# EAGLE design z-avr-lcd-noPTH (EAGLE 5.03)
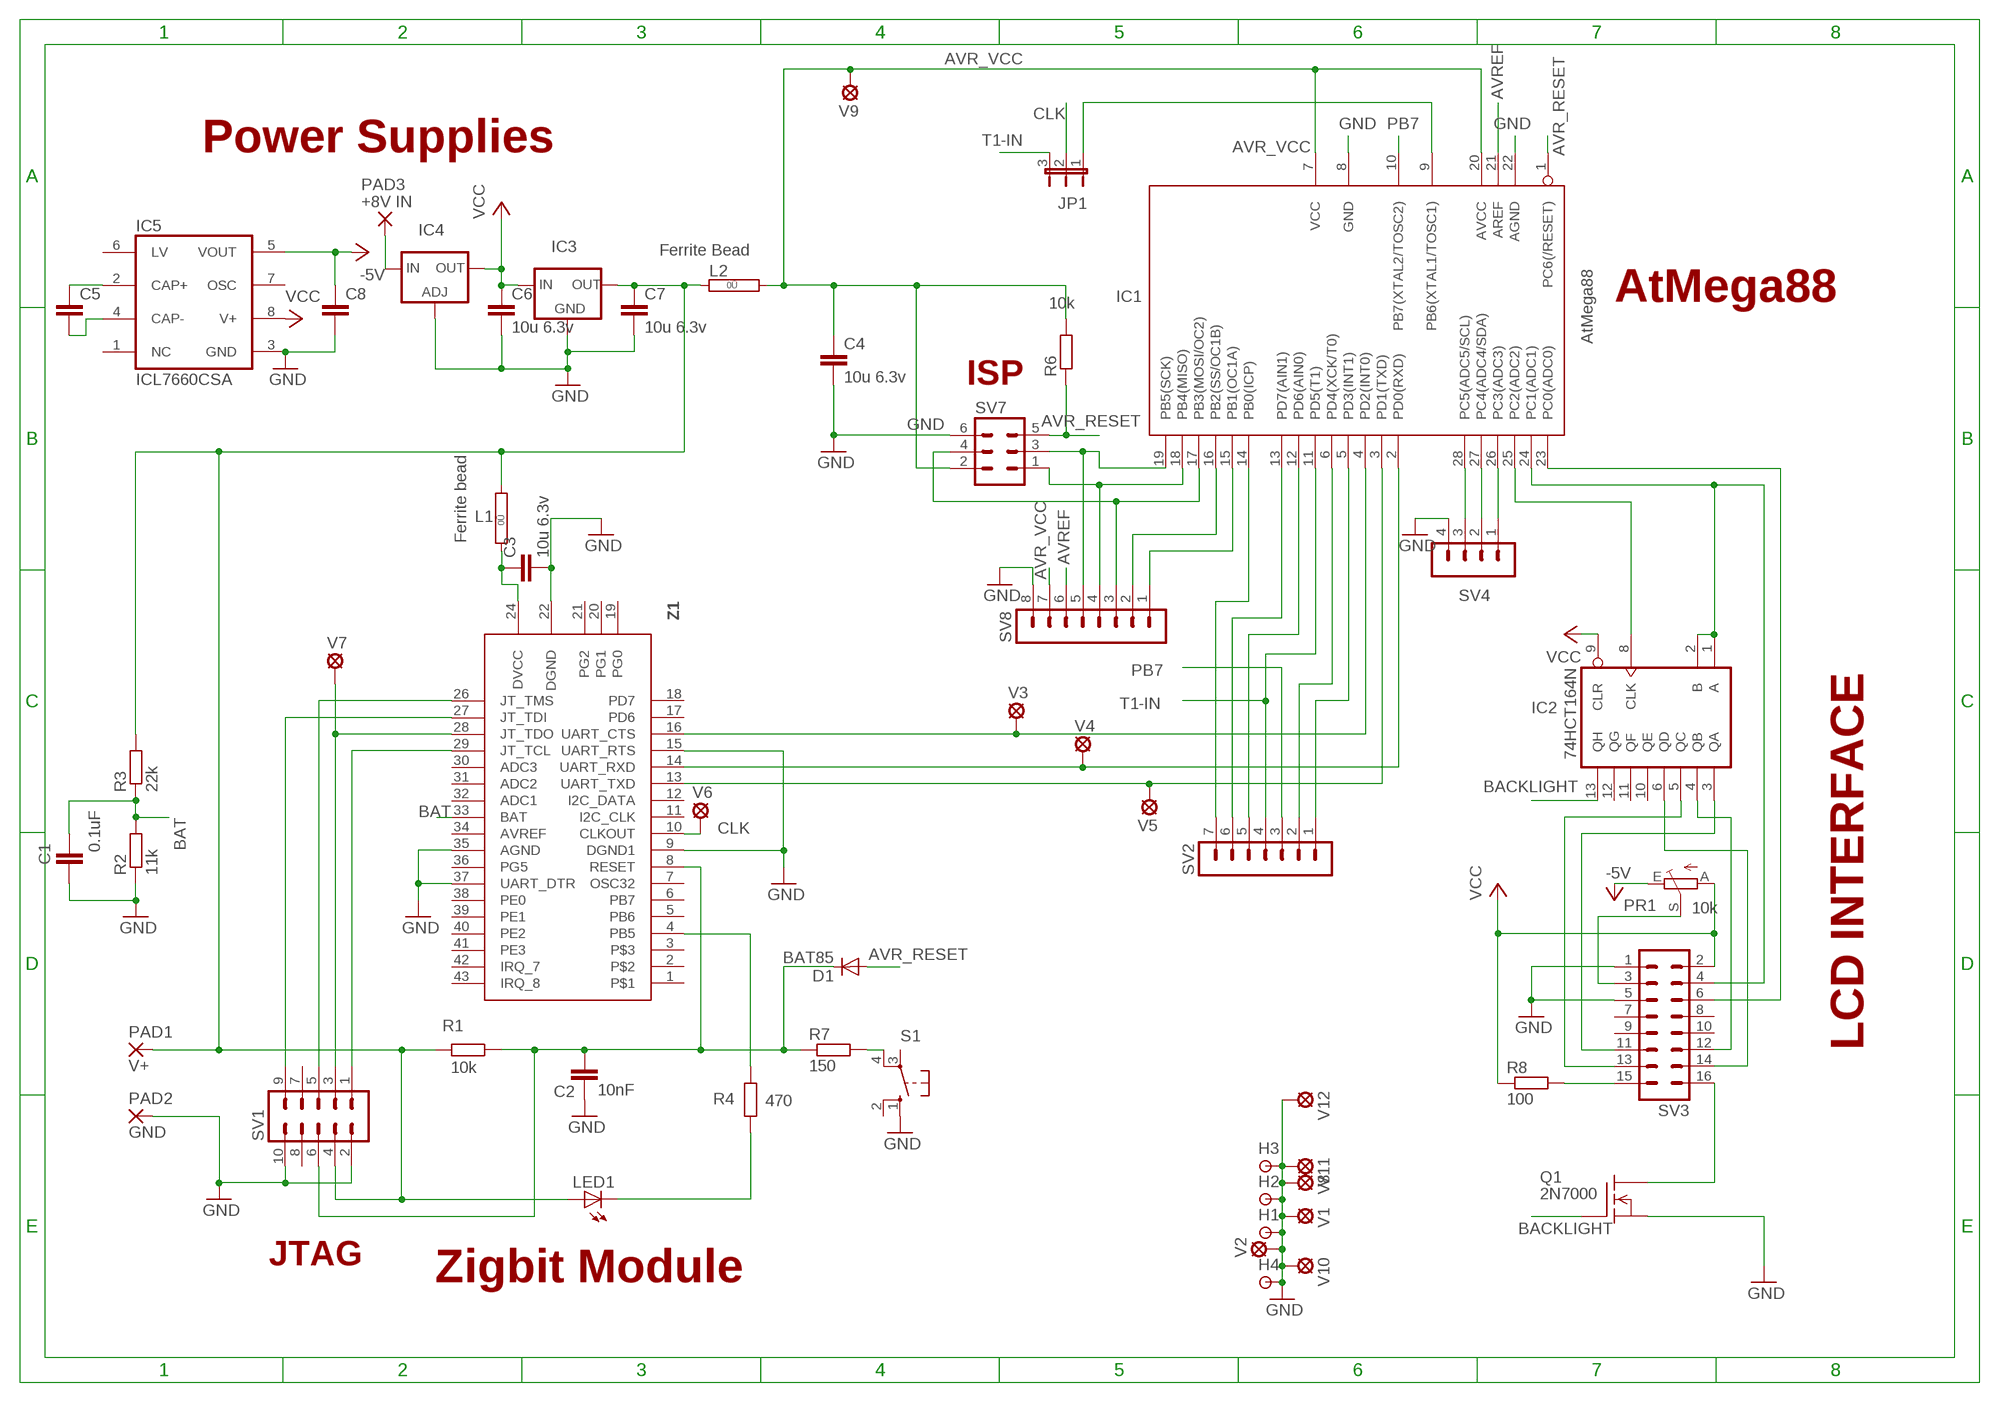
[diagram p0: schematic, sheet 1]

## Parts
C1  0.1uF  C5P  [C050-030-075]
C2  10nF  C5P  [C050-030-075]
C3  10u 6.3v  C-EUC1206  [C1206]
C4  10u 6.3v  C-EUC1206  [C1206]
C5  C-EUC1206  [C1206]
C6  10u 6.3v  C-EUC1206  [C1206]
C7  10u 6.3v  C-EUC1206  [C1206]
C8  C-EUC1206  [C1206]
D1  BAT85  1N4148  [DO34-7]
H1  HOLE/SMALL  [1,6/0,8]
H2  HOLE/SMALL  [1,6/0,8]
H3  HOLE/SMALL  [1,6/0,8]
H4  HOLE/SMALL  [1,6/0,8]
IC1  AtMega88  MEGA8-P  [DIL28-3]
IC2  74HCT164N  74ACT164N  [DIL14]
IC3  MC1702-3302E/TO 3.3V LDO VREG  XC63FPT  [TO92]
IC4  LD117ADT50TR  [DPACK]
IC5  ICL7660CSA  [SO08]
JP1  3 way Jumper  JP2E  [JP2]
L1  Ferrite bead  0R  [0R/10]
L2  Ferrite Bead  JUMPER_0R  [JUMPER_0R/10]
LED1  3MM red LED  LED-3MM3MM  [HLMP-D105]
PAD1  V+  TERMINAL-PAD  [2,54/1,1]
PAD2  GND  TERMINAL-PAD  [2,54/1,1]
PAD3  +8V IN  PAD-TERMINAL  [2,54/1,1]
PR1  10k  VAR_RESISTOR_TRIMS63P  [S63P]
Q1  2N7000  [TO92]
R1  10k  R  [0207/10]
R2  11k  R  [0207/10]
R3  22k  R  [0207/10]
R4  470  R  [0207/10]
R6  10k  R  [0207/10]
R7  150  R  [0207/10]
R8  100  R  [0207/10]
S1  BW3-1000 PCB pushbutton  10-XX  [B3F-10XX]
SV1  10 way IDC header  ML10  [ML10]
SV2  7 way pin header  MA07-1  [MA07-1]
SV3  16 way IDC mail header  ML16  [ML16]
SV4  4 way pin header  MA04-1  [MA04-1]
SV7  6 pin IDC male header  ML6  [ML6]
SV8  8 way pin header  MA08-1  [MA08-1]
V1  HOLE/VIA  [LSP10]
V2  HOLE-VIA  [LSP10]
V3  HOLE-VIA  [LSP10]
V4  HOLE-VIA  [LSP10]
V5  HOLE-VIA  [LSP10]
V6  HOLE-VIA  [LSP10]
V7  HOLE-VIA  [LSP10]
V8  HOLE-VIA  [LSP10]
V9  HOLE-VIA  [LSP10]
V10  HOLE-VIA  [LSP10]
V11  HOLE-VIA  [LSP10]
V12  HOLE-VIA  [LSP10]
Z1  ZDM-A1281-A2N  [ZIGSMD]

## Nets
-5V: C8.1 IC5.5(VOUT) PR1.E
AVR_RESET: D1.A IC1.1(PC6(/RESET)) R6.1 SV7.5
AVR_VCC [supply]: C4.1 IC1.7(VCC) IC1.20(AVCC) L2.2 R6.2 SV7.2 SV8.7 V9.MP
AVREF: IC1.21(AREF) SV8.6
BACKLIGHT: IC2.13(QH) Q1.2(G)
BAT: C1.2 R2.2 R3.1 Z1.33(BAT)
CLK: JP1.2 V6.MP Z1.10(CLKOUT)
GND [supply]: C1.1 C2.1 C3.2 C4.2 C6.2 C7.2 C8.2 H1.1(P) H2.1(P) H3.1(P) H4.1(P) IC1.8(GND) IC1.22(AGND) IC3.1(GND) IC4.1(ADJ) IC5.3(GND) PAD2.1(P) Q1.3(S) R2.1 S1.1(S) SV1.2 SV1.10 SV3.1 SV3.5 SV4.4 SV7.6 SV8.8 V1.MP V2.MP V8.MP V10.MP V11.MP V12.MP Z1.9(DGND1) Z1.15(UART_RTS) Z1.22(DGND) Z1.35(AGND) Z1.37(UART_DTR)
N$1: IC1.18(PB4(MISO)) SV7.1 SV8.4
N$2: IC1.19(PB5(SCK)) SV7.3 SV8.5
N$3: IC1.24(PC1(ADC1)) IC2.1(A) IC2.2(B) SV3.4
N$4: IC1.25(PC2(ADC2)) IC2.8(CLK)
N$5: IC1.28(PC5(ADC5/SCL)) SV4.3
N$6: R7.2 S1.4(P1)
N$7: IC1.27(PC4(ADC4/SDA)) SV4.2
N$8: IC1.17(PB3(MOSI/OC2)) SV7.4 SV8.3
N$9: SV1.5 Z1.26(JT_TMS)
N$10: SV1.1 Z1.29(JT_TCL)
N$11: SV1.3 V7.MP Z1.28(JT_TDO)
N$12: IC1.26(PC3(ADC3)) SV4.1
N$13: C2.2 D1.C R1.2 R7.1 SV1.6 Z1.8(RESET)
N$14: IC2.6(QD) SV3.14
N$15: IC1.23(PC0(ADC0)) SV3.6
N$17: C5.1 IC5.2(CAP+)
N$18: IC1.4(PD2(INT0)) V3.MP Z1.16(UART_CTS)
N$19: PR1.S SV3.3
N$20: IC1.2(PD0(RXD)) V4.MP Z1.14(UART_RXD)
N$21: IC1.3(PD1(TXD)) V5.MP Z1.13(UART_TXD)
N$22: IC2.3(QA) SV3.11
N$23: IC2.4(QB) SV3.12
N$24: IC2.5(QC) SV3.13
N$25: C5.2 IC5.4(CAP-)
N$26: R8.2 SV3.15
N$27: Q1.1(D) SV3.16
N$28: R4.2 Z1.4(PB5)
N$29 [supply]: IC4.3(IN) PAD3.1(P)
N$30: LED1.K(C) R4.1
N$31: SV1.9 Z1.27(JT_TDI)
N$32: IC1.9(PB6(XTAL1/TOSC1)) JP1.1
N$33 [supply]: C3.1 L1.1 Z1.24(DVCC)
N$34 [supply]: C7.1 IC3.3(OUT) L1.2 L2.1 LED1.A PAD1.1(P) R1.1 R3.2 SV1.4
N$37: IC1.5(PD3(INT1)) SV2.1
N$38: IC1.15(PB1(OC1A)) SV8.1
N$39: IC1.16(PB2(SS/OC1B)) SV8.2
N$40: IC1.12(PD6(AIN0)) SV2.5
N$41: IC1.13(PD7(AIN1)) SV2.6
N$42: IC1.14(PB0(ICP)) SV2.7
N$44: IC1.6(PD4(XCK/T0)) SV2.2
PB7: IC1.10(PB7(XTAL2/TOSC2)) SV2.3
T1-IN: IC1.11(PD5(T1)) JP1.3 SV2.4
VCC [supply]: C6.1 IC2.9(CLR) IC3.2(IN) IC4.4(OUT) IC5.8(V+) PR1.A R8.1 SV3.2
Unconnected: IC2.10(QE) IC2.11(QF) IC2.12(QG) IC5.1(NC) IC5.6(LV) IC5.7(OSC) S1.2(S1) S1.3(P) SV1.7 SV1.8 SV3.7 SV3.8 SV3.9 SV3.10 Z1.1 Z1.2 Z1.3 Z1.5(PB6) Z1.6(PB7) Z1.7(OSC32) Z1.11(I2C_CLK) Z1.12(I2C_DATA) Z1.17(PD6) Z1.18(PD7) Z1.19(PG0) Z1.20(PG1) Z1.21(PG2) Z1.30(ADC3) Z1.31(ADC2) Z1.32(ADC1) Z1.34(AVREF) Z1.36(PG5) Z1.38(PE0) Z1.39(PE1) Z1.40(PE2) Z1.41(PE3) Z1.42(IRQ_7) Z1.43(IRQ_8)

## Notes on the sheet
- Power Supplies
- AtMega88
- ISP
- LCD INTERFACE
- JTAG
- Zigbit Module

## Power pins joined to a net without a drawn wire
GND: IC2.7(GND)
VCC: IC2.14(VCC)

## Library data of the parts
C1 C2 = ee2parts:C: Capacitor
C3-C8 = rcl:C-EU: CAPACITOR, European symbol
D1 = ee2parts:1N4148: DIODE
H1-H4 = ee2parts:HOLE/SMALL: SMALL THROUGH-HOLE PAD/TESTPOINT
IC1 = atmel:MEGA8-P: MICROCONTROLLER 8 Kbytes FLASH, 1 kbytes SRAM, 512 bytes EEPROM, USART, 4-channel 10 bit ADC, 2-channel 8 bit ADC Pin compatible with Atmega48, ATMega88, ATMega168 Source: avr.lbr
IC2 = 74xx-eu:74*164: 8-bit parallel out SHIFT REGISTER
IC3 = v-reg:XC63FP: Positiv Voltage Regulators www.torex.co.jp/english/product/pro02/pdf/0201_xc62fp.pdf
IC4 = v-reg:LD117A?*: Low drop fixed and adjustable positive voltage regulators 1 A Source: http://www.st.com/stonline/products/literature/ds/7194/ld1117axx.pdf
IC5 = maxim:ICL7660CSA: VOLTAGE CONVERTER
JP1 = jumper:JP2E: JUMPER
L1 = jumper:0R: Bridge 0R 10mm
L2 = z-avr-lcd-noPTH:JUMPER_0R: Bridge 0R 10mm
LED1 = ee2parts:LED-3MM: LED
PAD1 PAD2 = ee2parts:TERMINAL-PAD: LARGE THROUGH-HOLE PAD
PAD3 = ee2parts:PAD-TERMINAL: LARGE THROUGH-HOLE PAD
PR1 = ee2parts:VAR_RESISTOR_TRIM: Variable resistor / potentiometer Trimmer potentiometer - Note that slider to end makes variable resistance
Q1 = z-avr-lcd-noPTH:2N7000: N-Channel Enhancement MOSFET 200V; 0,16A; 11Ohm
R1-R4 R6-R8 = ee2parts:R: Resistor
S1 = switch-omron:10-XX: OMRON SWITCH
SV1 = con-harting-ml:ML10: HARTING
SV2 = con-lstb:MA07-1: PIN HEADER
SV3 = con-ml:ML16: HARTING
SV4 = con-lstb:MA04-1: PIN HEADER
SV7 = con-harting-ml:ML6: HARTING
SV8 = con-lstb:MA08-1: PIN HEADER
V1 = ee2parts:HOLE/VIA: FIXED VIA
V2-V12 = ee2parts:HOLE-VIA: FIXED VIA
Z1 = ee2parts:ZDM-A1281-A2

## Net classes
1 supply: width 0.635 mm

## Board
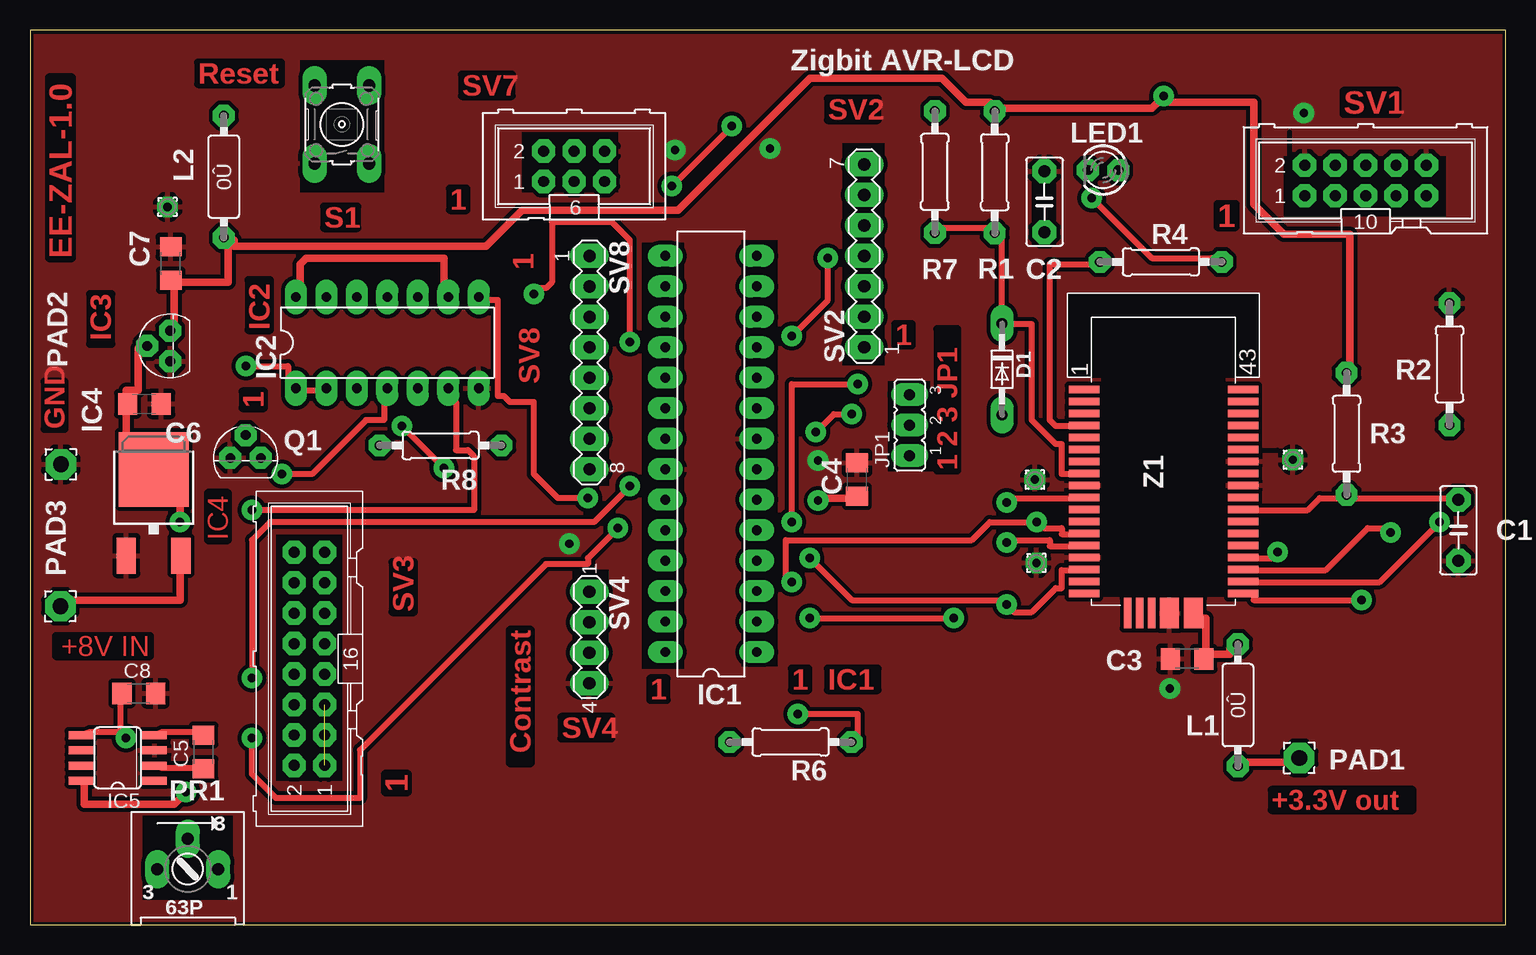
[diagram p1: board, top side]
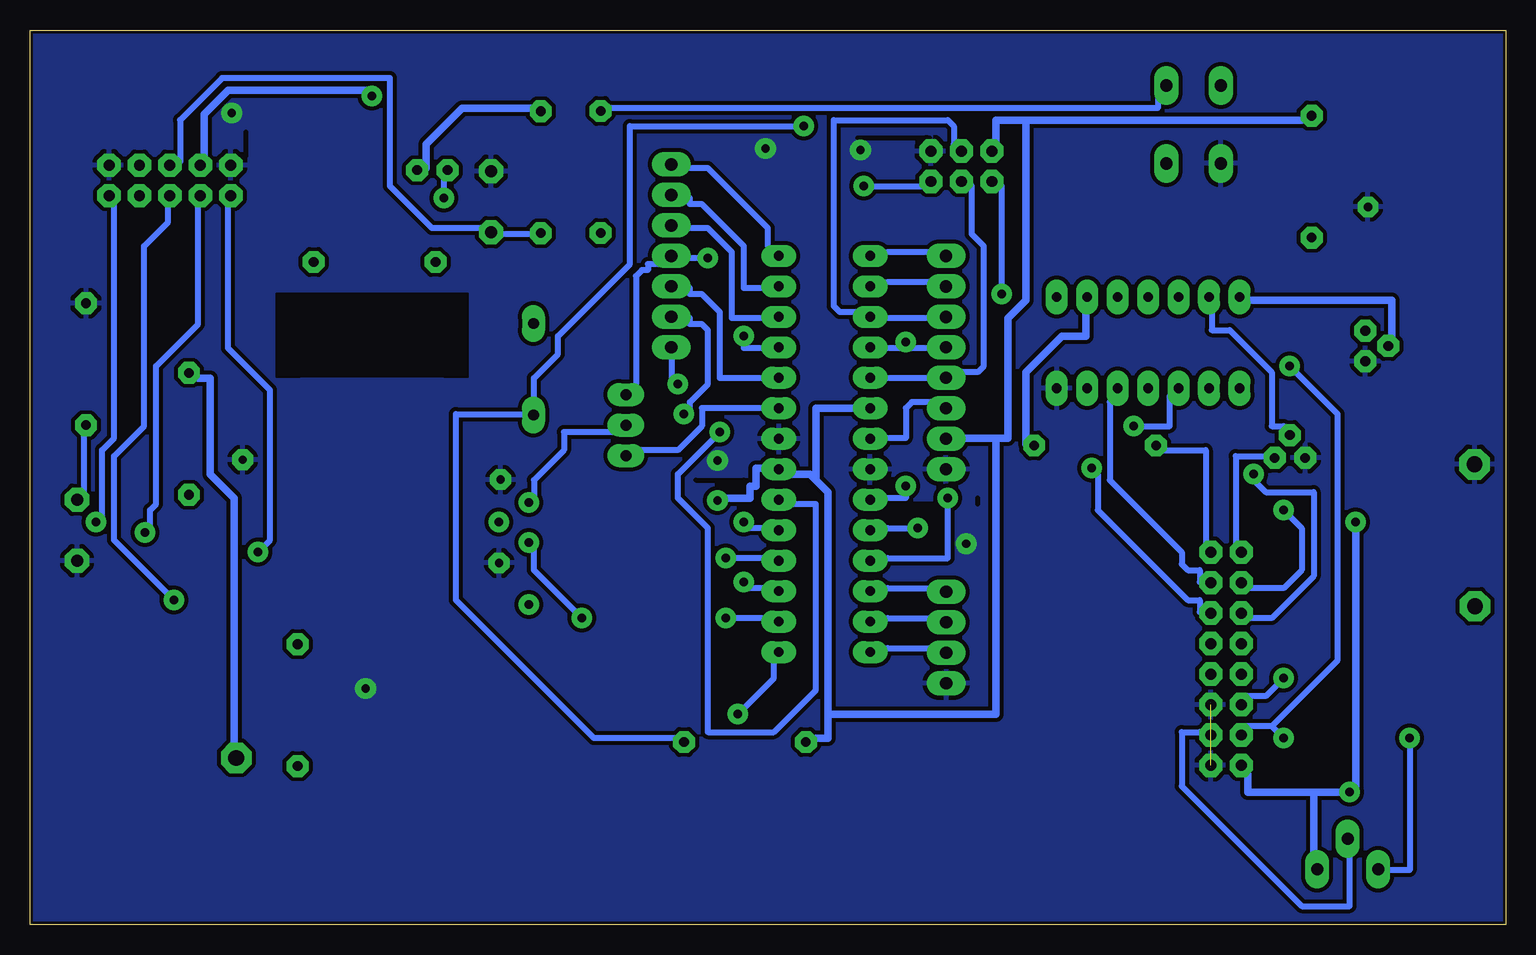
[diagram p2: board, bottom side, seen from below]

Size 123 x 74.58 mm. Coordinates in mm from the lower left corner, seen from the top.
Outline: 0,0 123,0 123,74.58 0,74.58 0,0
Copper layers (1*16): Top 0.035mm / dielectric 1.5mm / Bottom 0.035mm
Design rules "zigbit_rules *": minimum track width 20mil, minimum drill 0.7mm, track to track 13mil, track to pad 13mil, pad to pad 13mil, via to via 13mil, smd to smd 0mil, copper to edge 10mil, drill to drill 10mil, minimum pad ring 20mil, minimum via ring 20mil, stop-mask expansion 0mil, vias tented up to drill 0mil, thermal gap 15mil
tRestrict: area 104.5,59.1 to 118,64.1; area 87.2,62.1 to 91.7,63.6; area 83.5,56.6 to 85.5,63.6; area 41,61.1 to 49,66.1; area 67.7,46.7 to 71.2,65.2; area 22.5,61.1 to 29.5,72.1; area 44.8,36.6 to 48.3,57.1; area 20.5,12 to 26,32.5; area 9.4,2.1 to 16.9,9.1; area 51,21.3 to 54.5,56.8; area 59.3,21.5 to 62.3,57; area 71.5,37.8 to 75,45.3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; 2 lines
bRestrict: 6 lines
vRestrict: area 19.5,8.1 to 29,36.6; area 37,58.6 to 52.5,68.6; area 101,56.6 to 121.5,66.6; area 8.5,-0.2 to 18.7,10

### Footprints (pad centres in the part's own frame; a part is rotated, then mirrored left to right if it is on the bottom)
C050-030-075 = drill 1 octagon: 1 -2.54,0; 2 2.54,0
C1206 = smd 1.6 x 1.8: 1 -1.4,0; 2 1.4,0
DO34-7 = drill 0.9 long: A 3.81,0; C -3.81,0
1,6/0,8 = drill 0.7 pad 1.6 octagon: 1 0,0
DIL28-3 = drill 0.813 long: 1 -16.51,-3.81; 2 -13.97,-3.81; 3 -11.43,-3.81; 4 -8.89,-3.81; 5 -6.35,-3.81; 6 -3.81,-3.81; 7 -1.27,-3.81; 8 1.27,-3.81; 9 3.81,-3.81; 10 6.35,-3.81; 11 8.89,-3.81; 12 11.43,-3.81; 13 13.97,-3.81; 14 16.51,-3.81; 15 16.51,3.81; 16 13.97,3.81; 17 11.43,3.81; 18 8.89,3.81; 19 6.35,3.81; 20 3.81,3.81; 21 1.27,3.81; 22 -1.27,3.81; 23 -3.81,3.81; 24 -6.35,3.81; 25 -8.89,3.81; 26 -11.43,3.81; 27 -13.97,3.81; 28 -16.51,3.81
DIL14 = drill 0.813 long: 1 -7.62,-3.81; 2 -5.08,-3.81; 3 -2.54,-3.81; 4 0,-3.81; 5 2.54,-3.81; 6 5.08,-3.81; 7 7.62,-3.81; 8 7.62,3.81; 9 5.08,3.81; 10 2.54,3.81; 11 0,3.81; 12 -2.54,3.81; 13 -5.08,3.81; 14 -7.62,3.81
TO92 = drill 0.813 octagon: 1 -1.27,0; 2 0,1.905; 3 1.27,0
DPACK = smd 1.6 x 3: 1 -2.28,-4.8; 3 2.28,-4.8 | smd 5.8 x 6.2: 4 0,2.38
SO08 = smd 0.66 x 2.032: 1 -1.905,-3.073; 2 -0.635,-3.073; 3 0.635,-3.073; 4 1.905,-3.073; 5 1.905,3.073; 6 0.635,3.073; 7 -0.635,3.073; 8 -1.905,3.073
JP2 = drill 0.914 long: 1 -2.54,0; 2 0,0; 3 2.54,0
0R/10 = drill 0.813 pad 1.6 octagon: 1 -5.08,0; 2 5.08,0
JUMPER_0R/10 = drill 0.813 pad 1.6 octagon: 1 -5.08,0; 2 5.08,0
HLMP-D105 = drill 0.8 octagon: A -1.27,0; K 1.27,0
2,54/1,1 = drill 1.3 pad 2.54 octagon: 1 0,0
S63P = drill 1 long: A 2.54,0; E -2.54,0; S 0,2.54
TO92' = drill 0.813 octagon: 1 1.27,0; 2 0,1.905; 3 -1.27,0
0207/10 = drill 0.8 octagon: 1 -5.08,0; 2 5.08,0
B3F-10XX = drill 1.016 long: 1 -3.251,2.261; 2 3.251,2.261; 3 -3.251,-2.261; 4 3.251,-2.261
ML10 = drill 0.914 octagon: 1 -5.08,-1.27; 2 -5.08,1.27; 3 -2.54,-1.27; 4 -2.54,1.27; 5 0,-1.27; 6 0,1.27; 7 2.54,-1.27; 8 2.54,1.27; 9 5.08,-1.27; 10 5.08,1.27
MA07-1 = drill 1.016 long: 1 -7.62,0; 2 -5.08,0; 3 -2.54,0; 4 0,0; 5 2.54,0; 6 5.08,0; 7 7.62,0
ML16 = drill 0.914 octagon: 1 -8.89,-1.27; 2 -8.89,1.27; 3 -6.35,-1.27; 4 -6.35,1.27; 5 -3.81,-1.27; 6 -3.81,1.27; 7 -1.27,-1.27; 8 -1.27,1.27; 9 1.27,-1.27; 10 1.27,1.27; 11 3.81,-1.27; 12 3.81,1.27; 13 6.35,-1.27; 14 6.35,1.27; 15 8.89,-1.27; 16 8.89,1.27
MA04-1 = drill 1.016 long: 1 -3.81,0; 2 -1.27,0; 3 1.27,0; 4 3.81,0
ML6 = drill 0.914 octagon: 1 -2.54,-1.27; 2 -2.54,1.27; 3 0,-1.27; 4 0,1.27; 5 2.54,-1.27; 6 2.54,1.27
MA08-1 = drill 1.016 long: 1 -8.89,0; 2 -6.35,0; 3 -3.81,0; 4 -1.27,0; 5 1.27,0; 6 3.81,0; 7 6.35,0; 8 8.89,0
LSP10 = drill 0.7 pad 1.016 round: MP 0,0
ZIGSMD = smd 0.635 x 2.54: 1 7,6.635; 2 6,6.635; 3 5,6.635; 4 4,6.635; 5 3,6.635; 6 2,6.635; 7 1,6.635; 8 0,6.635; 9 -1,6.635; 10 -2,6.635; 11 -3,6.635; 12 -4,6.635; 13 -5,6.635; 14 -6,6.635; 15 -7,6.635; 16 -8,6.635; 17 -9,6.635; 18 -10,6.635; 26 -10,-6.635; 27 -9,-6.635; 28 -8,-6.635; 29 -7,-6.635; 30 -6,-6.635; 31 -5,-6.635; 32 -4,-6.635; 33 -3,-6.635; 34 -2,-6.635; 35 -1,-6.635; 36 0,-6.635; 37 1,-6.635; 38 2,-6.635; 39 3,-6.635; 40 4,-6.635; 41 5,-6.635; 42 6,-6.635; 43 7,-6.635 | smd 2.54 x 0.635: 19 -11.635,3; 20 -11.635,2; 21 -11.635,1 | smd 2.54 x 1.6: 22 -11.635,-0.5; 24 -11.635,-2.5

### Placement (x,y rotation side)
C1  119.08,32.89 90 top
C2  84.57,60.27 270 top
C3  96.46,22.17 180 top
C4  68.94,37.12 90 top
C5  14.47,14.42 90 top
C6  9.54,43.42 0 top
C7  11.74,55.12 90 top
C8  9.07,19.3 0 top
D1  81.03,46.31 270 top
H1  105.27,38.77 0 top
H2  11.47,59.84 0 top
H3  83.77,37.11 0 top
H4  83.9,30.17 0 top
IC1  56.77,39.25 90 top
IC2  29.79,48.53 0 top
IC3  11.68,48.25 90 top
IC4  10.31,35.58 0 top
IC5  7.31,13.92 90 top
JP1  73.32,41.65 90 top
L1  100.69,18.32 270 top
L2  16.16,62.36 90 top
LED1  89.46,62.9 180 top
PAD1  105.81,13.92 0 top
PAD2  2.58,38.39 90 top
PAD3  2.54,26.56 0 top
PR1  13.15,4.66 0 top
Q1  2N7000  [TO92']  17.97,38.92 0 top
R1  80.42,62.73 270 top
R2  118.33,46.73 270 top
R3  109.75,40.93 90 top
R4  94.27,55.25 180 top
R6  63.4,15.24 180 top
R7  75.43,62.75 90 top
R8  34.22,39.96 180 top
S1  26,66.71 90 top
SV1  111.34,62.05 0 top
SV2  69.55,55.75 90 top
SV3  23.29,22.18 90 top
SV4  46.62,23.96 270 top
SV7  45.36,63.23 0 top
SV8  46.64,46.86 270 top
V1  53.77,64.58 0 top
V2  95.02,19.69 0 top
V3  81.43,26.69 0 top
V4  81.43,31.88 0 top
V5  83.93,33.57 0 top
V6  81.43,35.19 0 top
V7  113.43,32.69 0 top
V8  65.69,38.69 0 top
V9  65.69,35.38 0 top
V10  61.69,64.69 0 top
V11  106.19,67.65 0 top
V12  44.95,31.76 0 top
Z1  94.49,37.62 90 top

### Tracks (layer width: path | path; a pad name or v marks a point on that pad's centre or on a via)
-5V  (via drill 0.7)
  Top 0.508: 7.5,16.08 7.5,18.58 C8.1 | 7.5,16.08 5,16.08 IC5.5 | 7.5,16.08 v8,15.58
  Bottom 0.508: v8,15.58 8,4.58 10,4.58 PR1.E
AVR_RESET  (via drill 0.7)
  Top 0.508: v64,17.58 69,17.58 69,15.58 R6.1 | v58.5,66.58 v53.5,61.58
  Bottom 0.508: v64,17.58 61,20.58 61,22.08 IC1.1 | R6.1 69,15.58 76,15.58 87.5,27.08 87.5,42.58 81.5,42.58 D1.A 81,43.58 81,45.58 79,47.58 79,49.08 73,55.08 73,66.58 v58.5,66.58 | v53.5,61.58 48.5,61.58 SV7.5
AVR_VCC
  Top 0.635: C4.1 68.5,35.58 66.5,35.58 V9.MP
  Bottom 0.635: 56.5,17.58 56.5,36.08 57.5,37.08 | 56.5,17.58 56.5,15.58 57.5,15.58 R6.2 | 57.5,37.08 58,37.58 59.5,37.58 IC1.7 62,38.08 62.5,38.08 62.5,36.58 63,36.58 63,35.58 65,35.58 V9.MP | 57.5,37.08 57.5,43.08 54,43.08 IC1.20 | 40,67.08 42.5,67.08 42.5,65.08 SV7.2 | 40,67.08 17,67.08 L2.2 | 42.5,40.58 41.5,40.58 41.5,50.58 40,52.08 40,67.08 | 42.5,40.58 45.5,40.58 SV8.7 | 56.5,17.58 42.5,17.58 42.5,40.58
AVREF
  Bottom 0.508: IC1.21 51.5,40.58 50,40.58 50,43.08 49.5,43.58 48,43.58 SV8.6
BACKLIGHT
  Bottom 0.508: Q1.2 18.5,41.58 19.5,41.58 19.5,46.08 23,49.58 24.5,49.58 24.5,51.08 IC2.13
BAT
  Top 0.508: Z1.33 102,34.58 106.5,34.58 107.5,35.58 109,35.58 R3.1 110.5,35.58 118.5,35.58 C1.2
  Bottom 0.508: R2.2 118.5,41.08 118.5,36.08 C1.2
CLK
  Top 0.508: Z1.10 87,35.58 82,35.58 V6.MP
  Bottom 0.508: JP1.2 74.5,41.08 78.5,41.08 78.5,39.58 81,37.08 81,35.58 V6.MP
GND  (1 unrouted)
  pour Bottom: 0,74.08 123,74.08 123,0 0,0
  pour Top: 0,74.08 123,74.08 123,0 0,0
N$1  (via drill 0.7)
  Top 0.508: v42,52.58 42.5,53.08 43,53.08 43.5,53.58 43.5,58.58 48.5,58.58 50,57.08 v50,48.58
  Bottom 0.508: 50,48.08 48,48.08 SV8.4 | 50,48.08 51.5,48.08 IC1.18 | v42,52.58 42,61.58 SV7.1 | 50,48.08 v50,48.58
N$2
  Bottom 0.508: IC1.19 51.5,45.58 48,45.58 SV8.5 45.5,46.08 44,46.08 43.5,46.58 43.5,56.58 44.5,57.58 44.5,61.58 SV7.3
N$3  (via drill 0.7)
  Top 0.508: IC2.2 24,44.58 23,44.58 IC2.1 21.5,45.58 21.5,46.58 v18,46.58 | v49,33.08 46.5,30.58 46.5,30.08 43,30.08 27.5,14.58 27.5,10.58 20.5,10.58 18.5,12.58 v18.5,15.58
  Bottom 0.508: v49,33.08 51.5,33.08 IC1.24 | v18.5,15.58 19.5,16.58 | 19.5,16.58 21.5,16.58 SV3.4 | v18,46.58 14,42.58 14,22.08 19.5,16.58
N$4  (via drill 0.7)
  Top 0.508: v46.5,35.58 44,35.58 42,37.58 42,43.58 40,43.58 39.5,44.08 39,44.08 39,52.08 38,52.08 IC2.8
  Bottom 0.508: v46.5,35.58 46.5,30.58 51.5,30.58 IC1.25
N$5
  Bottom 0.508: IC1.28 51.5,23.08 48,23.08 SV4.3
N$6
  Bottom 0.508: R7.2 75,68.08 29,68.08 29,69.08 S1.4
N$7
  Bottom 0.508: IC1.27 51.5,25.58 48,25.58 SV4.2
N$8
  Bottom 0.508: SV8.3 48,50.58 51.5,50.58 IC1.17 54,51.08 55.5,51.08 56,51.58 56,67.08 46.5,67.08 46,66.58 46,65.08 SV7.4
N$9  (via drill 0.7)
  Top 0.508: v111,27.08 102,27.08 102,27.58 Z1.26
  Bottom 0.508: v111,27.08 116,32.08 116,39.08 113.5,41.58 113.5,56.58 111.5,58.58 111.5,60.08 SV1.5
N$10  (via drill 0.7)
  Top 0.508: v104,31.08 103.5,30.58 102,30.58 Z1.29
  Bottom 0.508: v104,31.08 103,32.08 103,44.58 106.5,48.08 106.5,60.08 SV1.1
N$11
  Top 0.508: Z1.28 102,29.58 108,29.58 111.5,33.08 113,33.08 V7.MP
  Bottom 0.508: SV1.3 109,60.08 109,50.08 112.5,46.58 112.5,35.08 113,34.58 113,33.08 V7.MP
N$12
  Bottom 0.508: IC1.26 51.5,28.08 48,28.08 SV4.1
N$13
  Top 0.508: Z1.8 87,37.58 86,37.58 86,40.08 85.5,40.08 83.5,42.08 83.5,50.08 81.5,50.08 D1.C 81,51.58 81,57.08 R1.2 80,58.08 76,58.08 R7.1
  Bottom 0.508: R1.2 81,57.58 84,57.58 C2.2 85.5,58.08 89.5,58.08 93,61.58 93,70.58 107,70.58 110.5,67.08 110.5,63.58 SV1.6
N$14  (via drill 0.7)
  Top 0.508: v18.5,34.58 37,34.58 37,39.08 36.5,39.58 35.5,39.58 35.5,43.58 IC2.6
  Bottom 0.508: v18.5,34.58 17,33.08 17,29.58 18.5,28.08 21.5,28.08 SV3.14
N$15  (via drill 0.7)
  Top 0.508: v50,36.58 47,33.58 20,33.58 18.5,32.08 v18.5,20.58
  Bottom 0.508: v50,36.58 50,35.58 51.5,35.58 IC1.23 | v18.5,20.58 20,19.08 21.5,19.08 SV3.6
N$17
  Top 0.508: C5.1 14,13.08 11,13.08 IC5.2
N$18  (via drill 0.7)
  Top 0.508: Z1.16 87,29.58 86,29.58 86,28.08 85.5,28.08 83.5,26.08 82,26.08 V3.MP 81,27.08 68.5,27.08 v65,30.58
  Bottom 0.508: v65,30.58 62,30.58 IC1.4
N$19
  Bottom 0.508: SV3.3 25.5,16.08 27,16.08 27,11.58 17,1.58 13,1.58 13,6.08 PR1.S
N$20  (via drill 0.7)
  Top 0.508: Z1.14 87,31.58 85,31.58 85,32.08 82,32.08 V4.MP | v65,25.58 v77,25.58
  Bottom 0.508: v65,25.58 62,25.58 IC1.2 | v77,25.58 81,29.58 81,31.58 V4.MP
N$21  (via drill 0.7)
  Top 0.508: Z1.13 87,32.58 86,32.58 86,33.08 84.5,33.08 V5.MP 83.5,33.58 80,33.58 78.5,32.08 63,32.08 63,29.08 63.5,29.08 v63.5,28.58
  Bottom 0.508: v63.5,28.58 63.5,28.08 62,28.08 IC1.3
N$22  (via drill 0.7)
  Top 0.508: v34.5,38.08 v31,41.58
  Bottom 0.508: v31,41.58 28,41.58 28,44.08 IC2.3 | v34.5,38.08 34,37.58 34,34.58 26.5,27.08 25.5,27.08 25.5,26.08 SV3.11
N$23  (via drill 0.7)
  Top 0.508: v21,37.58 23.5,37.58 28,42.08 29.5,42.08 29.5,43.58 IC2.4
  Bottom 0.508: v21,37.58 21,37.08 20,36.08 16,36.08 16,29.08 19.5,25.58 21.5,25.58 SV3.12
N$24
  Bottom 0.508: IC2.5 33,43.58 33,37.08 27,31.08 27,30.08 26.5,29.58 25.5,29.58 25.5,28.58 SV3.13
N$25
  Top 0.508: C5.2 14,16.08 11,16.08 IC5.4
N$26
  Bottom 0.508: R8.2 28.5,39.58 25,39.58 25,31.58 SV3.15
N$27
  Bottom 0.508: Q1.1 20,39.08 22.5,39.08 22.5,31.58 SV3.16
N$28
  Top 0.508: Z1.4 87,41.58 85.5,41.58 85,42.08 85,55.08 88.5,55.08 R4.2
N$29
  Top 0.635: IC4.3 12.5,29.58 12.5,27.08 3.5,27.08 PAD3.1
N$30  (via drill 0.7)
  Top 0.508: v88.5,60.58 93.5,55.58 98.5,55.58 R4.1
  Bottom 0.508: v88.5,60.58 88.5,62.08 LED1.K
N$31  (via drill 0.7)
  Top 0.508: v117.5,33.58 112.5,28.58 102,28.58 Z1.27
  Bottom 0.508: v117.5,33.58 117,34.08 117,39.58 116,40.58 116,60.08 SV1.9
N$32
  Bottom 0.508: IC1.9 62,43.08 67,43.08 67,41.58 69,39.58 72,39.58 JP1.1
N$33
  Top 0.635: Z1.24 97.5,25.58 98,25.58 98,22.58 C3.1 98.5,22.58 100,22.58 100,23.08 L1.1
N$34  (via drill 0.7)
  Top 0.635: L1.2 101.5,13.58 105,13.58 PAD1.1 | IC3.3 12,50.08 12,53.08 C7.1 12.5,53.58 16.5,53.58 16.5,56.58 L2.1 17,57.08 17,56.58 38,56.58 41,59.58 54,59.58 65,70.58 76,70.58 78,68.58 80,68.58 R1.1 81,68.08 93.5,68.08 v94.5,69.08 95,68.58 102,68.58 102,60.08 104.5,57.58 110,57.58 110,46.58 R3.2
  Bottom 0.635: R3.2 109,45.58 108,45.58 108,37.58 106,35.58 106,15.08 PAD1.1 | LED1.A 90,63.08 90,65.08 87,68.08 81,68.08 R1.1 | v94.5,69.08 94.5,69.58 106.5,69.58 108.5,67.58 108.5,64.08 SV1.4
N$37  (via drill 0.7)
  Top 0.508: v63.5,33.58 63.5,45.08 v69,45.08
  Bottom 0.508: v63.5,33.58 63.5,33.08 62,33.08 IC1.5 | v69,45.08 69.5,45.58 69.5,47.58 SV2.1
N$38
  Bottom 0.508: IC1.15 51.5,56.08 48,56.08 SV8.1
N$39
  Bottom 0.508: IC1.16 51.5,53.58 48,53.58 SV8.2
N$40
  Bottom 0.508: IC1.12 62,50.58 64.5,50.58 64.5,56.08 66.5,58.08 68,58.08 SV2.5
N$41
  Bottom 0.508: IC1.13 62,53.08 63.5,53.08 63.5,56.58 67,60.08 68,60.08 68,60.58 SV2.6
N$42
  Bottom 0.508: IC1.14 61.5,56.58 61.5,58.08 66.5,63.08 68,63.08 SV2.7
N$44  (via drill 0.7)
  Top 0.508: v65.5,41.08 67,42.58 v68.5,42.58
  Bottom 0.508: v65.5,41.08 69,37.58 69,35.58 66.5,33.08 66.5,16.08 61,16.08 57.5,19.58 57.5,35.08 59.5,35.08 IC1.6 | v68.5,42.58 68,43.08 68,43.58 66.5,45.08 66.5,49.58 67,50.08 68,50.08 68,50.58 SV2.2
PB7
  Bottom 0.508: IC1.10 62,45.58 65.5,45.58 65.5,51.08 67,52.58 68,52.58 68,53.08 SV2.3
T1-IN  (via drill 0.7)
  Top 0.508: v63.5,49.08 66.5,52.08 v66.5,55.58
  Bottom 0.508: v63.5,49.08 63.5,48.08 62,48.08 IC1.11 | v66.5,55.58 68,55.58 SV2.4 70.5,55.08 71.5,55.08 71.5,54.58 72,54.58 72.5,54.08 72.5,45.08 JP1.3
VCC  (via drill 0.7)
  Top 0.635: v13,11.08 12,10.08 4.5,10.08 4.5,12.08 IC5.8 | IC3.2 9,48.08 9,44.58 8,44.58 8,44.08 C6.1 8,42.58 8,40.58 IC4.4 12.5,35.08 v12.5,33.58 | IC2.9 34.5,53.58 34.5,55.58 23,55.58 22.5,55.08 22.5,53.58 IC2.14
  Bottom 0.635: 16,11.08 21.5,11.08 21.5,12.58 SV3.2 | 16,11.08 v13,11.08 12.5,11.58 v12.5,33.58 | 16,11.08 16,6.08 PR1.A | R8.1 40,40.08 40,46.08 37,49.08 35,49.08 35,51.08 IC2.9 | IC2.14 21.5,52.08 9.5,52.08 9.5,49.08 IC3.2

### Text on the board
Top: Reset | SV7 | SV2 | 1 | 1 | S1 | EE-ZAL-1.0 | 1 | IC3 | 1 | IC2 | SV8 | 1 | 1 2 3 JP1 | IC4 | SV3 | Contrast | +8V IN | 1 | 1 | IC1 | SV4 | 1 | +3.3V out
tPlace: Zigbit AVR-LCD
